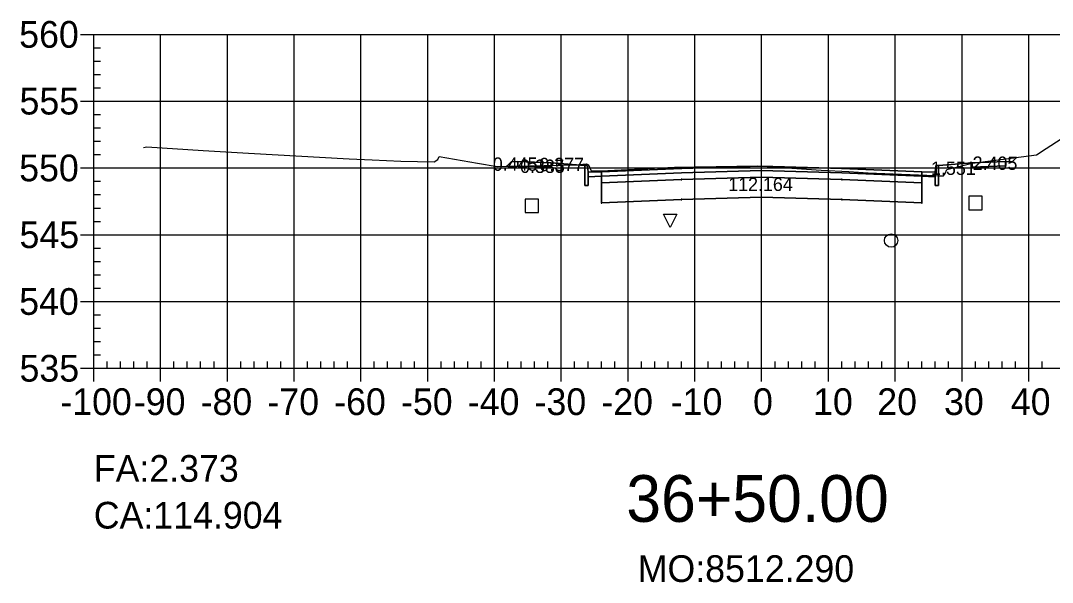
# Model space of a CAD drawing. Extents: x 704834 to 709892, y 372981 to 377533.
# Drawn here: x 707125.9 to 707280.4, y 373920.8 to 374004.9 of the extents above; entities that cross this region are included whole.
import ezdxf

# ---------------------------------------------------------------- set-up
doc = ezdxf.new("R2010")
doc.units = 0
for name, color, linetype in [('1', 7, 'Continuous'), ('10', 7, 'Continuous'), ('13', 7, 'Continuous'), ('14', 7, 'Continuous'), ('4', 7, 'Continuous'), ('57', 7, 'Continuous'), ('59', 7, 'Continuous'), ('Default_Xsect', 7, 'Continuous'), ('Existing', 7, 'Continuous')]:
    doc.layers.add(name, color=color, linetype=linetype)

msp = doc.modelspace()

# ---------------------------------------------------------------- linework, layer by layer
for points in [[(707199.37, 373983.74), (707198.7, 373983.07)], [(707200.37, 373983.78), (707199.37, 373983.74)], [(707210.37, 373983.18), (707205.37, 373983.58)], [(707263.37, 373983.18), (707268.37, 373983.58)], [(707273.37, 373983.78), (707274.37, 373983.74)], [(707274.37, 373983.74), (707275.04, 373984.4)]]:
    msp.add_lwpolyline(points)
for points in [[(707205.37, 373983.58), (707200.37, 373983.78), (707200.37, 373983.11), (707205.37, 373982.91)], [(707210.87, 373982.18), (707210.79, 373983.18), (707210.37, 373983.18), (707210.37, 373980.18), (707210.87, 373980.18)], [(707236.87, 373982.43), (707248.87, 373982.07), (707260.87, 373981.59), (707260.87, 373982.26), (707248.87, 373982.74), (707236.87, 373983.1), (707224.87, 373982.74), (707212.87, 373982.26), (707212.87, 373981.59), (707224.87, 373982.07)], [(707262.87, 373980.18), (707263.37, 373980.18), (707263.37, 373983.18), (707262.96, 373983.18), (707262.87, 373982.18)], [(707268.37, 373982.91), (707273.37, 373983.11), (707273.37, 373983.78), (707268.37, 373983.58)], [(707212.87, 373982.26), (707210.87, 373982.18), (707210.87, 373981.51), (707212.87, 373981.59)], [(707236.87, 373981.43), (707248.87, 373981.07), (707260.87, 373980.59), (707260.87, 373981.59), (707248.87, 373982.07), (707236.87, 373982.43), (707224.87, 373982.07), (707212.87, 373981.59), (707212.87, 373980.59), (707224.87, 373981.07)], [(707236.87, 373978.43), (707248.87, 373978.07), (707260.87, 373977.59), (707260.87, 373980.59), (707248.87, 373981.07), (707236.87, 373981.43), (707224.87, 373981.07), (707212.87, 373980.59), (707212.87, 373977.59), (707224.87, 373978.07)], [(707236.82, 373982.38), (707236.92, 373982.38), (707236.92, 373982.48), (707236.82, 373982.48)], [(707236.82, 373981.38), (707236.92, 373981.38), (707236.92, 373981.48), (707236.82, 373981.48)], [(707260.87, 373981.59), (707262.87, 373981.51), (707262.87, 373982.18), (707260.87, 373982.26)], [(707212.82, 373980.54), (707212.92, 373980.54), (707212.92, 373980.64), (707212.82, 373980.64)], [(707224.82, 373981.02), (707224.92, 373981.02), (707224.92, 373981.12), (707224.82, 373981.12)], [(707248.82, 373981.02), (707248.92, 373981.02), (707248.92, 373981.12), (707248.82, 373981.12)], [(707260.82, 373980.54), (707260.92, 373980.54), (707260.92, 373980.64), (707260.82, 373980.64)], [(707236.82, 373978.38), (707236.92, 373978.38), (707236.92, 373978.48), (707236.82, 373978.48)], [(707212.82, 373977.54), (707212.92, 373977.54), (707212.92, 373977.64), (707212.82, 373977.64)], [(707224.82, 373978.02), (707224.92, 373978.02), (707224.92, 373978.12), (707224.82, 373978.12)], [(707248.82, 373978.02), (707248.92, 373978.02), (707248.92, 373978.12), (707248.82, 373978.12)], [(707260.82, 373977.54), (707260.92, 373977.54), (707260.92, 373977.64), (707260.82, 373977.64)]]:
    msp.add_lwpolyline(points, close=True)
at = {"layer": '1'}
for points in [[(707198.7, 373983.07), (707200.59, 373983.1), (707200.37, 373983.11), (707200.37, 373983.78), (707199.37, 373983.74)], [(707200.59, 373983.1), (707205.37, 373983.19), (707205.37, 373982.91)], [(707205.37, 373983.19), (707208.93, 373983.26), (707209.14, 373983.28), (707205.37, 373983.58)], [(707209.14, 373983.28), (707210.62, 373983.41), (707210.89, 373983.35), (707210.92, 373983.28), (707211.34, 373982.38), (707212.82, 373982.41), (707223.83, 373982.95), (707233.14, 373983.07), (707236.27, 373983.12), (707245.8, 373982.5), (707249.91, 373982.27), (707252.83, 373982.09), (707263.37, 373981.65), (707263.37, 373980.18), (707262.87, 373980.18), (707262.87, 373981.51), (707260.87, 373981.59), (707260.87, 373980.59), (707260.87, 373977.59), (707248.87, 373978.07), (707236.87, 373978.43), (707224.87, 373978.07), (707212.87, 373977.59), (707212.87, 373980.59), (707212.87, 373981.59), (707210.87, 373981.51), (707210.87, 373980.18), (707210.37, 373980.18), (707210.37, 373983.18)], [(707263.37, 373981.65), (707264.12, 373981.62), (707264.35, 373982.01), (707264.62, 373982.6), (707267.97, 373983.44), (707268.37, 373983.5), (707268.37, 373983.58), (707263.37, 373983.18)], [(707268.37, 373983.5), (707268.44, 373983.51), (707275.04, 373984.4), (707274.37, 373983.74), (707273.37, 373983.78), (707273.37, 373983.11), (707268.37, 373982.91)], [(707223.16, 373973.92), (707222.16, 373975.92), (707224.16, 373975.92)]]:
    msp.add_lwpolyline(points, close=True, dxfattribs=at)
at = {"layer": '10'}
msp.add_lwpolyline([(707201.46, 373976.14), (707203.46, 373976.14), (707203.46, 373978.14), (707201.46, 373978.14)], close=True, dxfattribs=at)
at = {"layer": '13'}
msp.add_circle((707256.26, 373971.95), 1, dxfattribs=at)
at = {"layer": '14'}
for points in [[(707198.7, 373983.07), (707198.7, 373983.12), (707198.7, 373983.07), (707198.65, 373983.07), (707198.7, 373983.07), (707198.7, 373983.02), (707198.7, 373983.07), (707198.75, 373983.07)], [(707236.87, 373983.1), (707236.87, 373983.15), (707236.87, 373983.1), (707236.82, 373983.1), (707236.87, 373983.1), (707236.87, 373983.05), (707236.87, 373983.1), (707236.92, 373983.1)], [(707275.04, 373984.4), (707275.04, 373984.45), (707275.04, 373984.4), (707274.99, 373984.4), (707275.04, 373984.4), (707275.04, 373984.35), (707275.04, 373984.4), (707275.09, 373984.4)], [(707212.87, 373982.26), (707212.87, 373982.31), (707212.87, 373982.26), (707212.82, 373982.26), (707212.87, 373982.26), (707212.87, 373982.21), (707212.87, 373982.26), (707212.92, 373982.26)], [(707224.87, 373982.74), (707224.87, 373982.79), (707224.87, 373982.74), (707224.82, 373982.74), (707224.87, 373982.74), (707224.87, 373982.69), (707224.87, 373982.74), (707224.92, 373982.74)], [(707248.87, 373982.74), (707248.87, 373982.79), (707248.87, 373982.74), (707248.82, 373982.74), (707248.87, 373982.74), (707248.87, 373982.69), (707248.87, 373982.74), (707248.92, 373982.74)], [(707260.87, 373982.26), (707260.87, 373982.31), (707260.87, 373982.26), (707260.82, 373982.26), (707260.87, 373982.26), (707260.87, 373982.21), (707260.87, 373982.26), (707260.92, 373982.26)]]:
    msp.add_lwpolyline(points, dxfattribs=at)
at = {"layer": '4'}
msp.add_lwpolyline([(707267.91, 373976.57), (707269.91, 373976.57), (707269.91, 373978.57), (707267.91, 373978.57)], close=True, dxfattribs=at)
at = {"layer": '57'}
for p, q in [((707134.87, 374002.82), (707136.87, 374002.82)), ((707136.87, 374002.82), (707336.87, 374002.82)), ((707136.87, 373952.82), (707136.87, 374002.82)), ((707136.87, 373952.82), (707136.87, 374002.82)), ((707146.87, 373952.82), (707146.87, 374002.82)), ((707156.87, 373952.82), (707156.87, 374002.82)), ((707166.87, 373952.82), (707166.87, 374002.82)), ((707176.87, 373952.82), (707176.87, 374002.82)), ((707186.87, 373952.82), (707186.87, 374002.82)), ((707196.87, 373952.82), (707196.87, 374002.82)), ((707206.87, 373952.82), (707206.87, 374002.82)), ((707216.87, 373952.82), (707216.87, 374002.82)), ((707226.87, 373952.82), (707226.87, 374002.82)), ((707236.87, 373952.82), (707236.87, 374002.82)), ((707246.87, 373952.82), (707246.87, 374002.82)), ((707256.87, 373952.82), (707256.87, 374002.82)), ((707266.87, 373952.82), (707266.87, 374002.82)), ((707276.87, 373952.82), (707276.87, 374002.82)), ((707136.87, 374000.82), (707137.87, 374000.82)), ((707136.87, 373998.82), (707137.87, 373998.82)), ((707136.87, 373996.82), (707137.87, 373996.82)), ((707136.87, 373994.82), (707137.87, 373994.82)), ((707134.87, 373992.82), (707136.87, 373992.82)), ((707136.87, 373992.82), (707336.87, 373992.82)), ((707136.87, 373990.82), (707137.87, 373990.82)), ((707136.87, 373988.82), (707137.87, 373988.82)), ((707136.87, 373986.82), (707137.87, 373986.82)), ((707136.87, 373984.82), (707137.87, 373984.82)), ((707134.87, 373982.82), (707136.87, 373982.82)), ((707136.87, 373982.82), (707336.87, 373982.82)), ((707136.87, 373980.82), (707137.87, 373980.82)), ((707136.87, 373978.82), (707137.87, 373978.82)), ((707136.87, 373976.82), (707137.87, 373976.82)), ((707136.87, 373974.82), (707137.87, 373974.82)), ((707134.87, 373972.82), (707136.87, 373972.82)), ((707136.87, 373972.82), (707336.87, 373972.82)), ((707136.87, 373970.82), (707137.87, 373970.82)), ((707136.87, 373968.82), (707137.87, 373968.82)), ((707136.87, 373966.82), (707137.87, 373966.82)), ((707136.87, 373964.82), (707137.87, 373964.82)), ((707134.87, 373962.82), (707136.87, 373962.82)), ((707136.87, 373962.82), (707336.87, 373962.82)), ((707136.87, 373960.82), (707137.87, 373960.82)), ((707136.87, 373958.82), (707137.87, 373958.82)), ((707136.87, 373956.82), (707137.87, 373956.82)), ((707136.87, 373954.82), (707137.87, 373954.82)), ((707138.87, 373952.82), (707138.87, 373953.82)), ((707140.87, 373952.82), (707140.87, 373953.82)), ((707142.87, 373952.82), (707142.87, 373953.82)), ((707144.87, 373952.82), (707144.87, 373953.82)), ((707148.87, 373952.82), (707148.87, 373953.82)), ((707150.87, 373952.82), (707150.87, 373953.82)), ((707152.87, 373952.82), (707152.87, 373953.82)), ((707154.87, 373952.82), (707154.87, 373953.82)), ((707158.87, 373952.82), (707158.87, 373953.82)), ((707160.87, 373952.82), (707160.87, 373953.82)), ((707162.87, 373952.82), (707162.87, 373953.82)), ((707164.87, 373952.82), (707164.87, 373953.82)), ((707168.87, 373952.82), (707168.87, 373953.82)), ((707170.87, 373952.82), (707170.87, 373953.82)), ((707172.87, 373952.82), (707172.87, 373953.82)), ((707174.87, 373952.82), (707174.87, 373953.82)), ((707178.87, 373952.82), (707178.87, 373953.82)), ((707180.87, 373952.82), (707180.87, 373953.82)), ((707182.87, 373952.82), (707182.87, 373953.82)), ((707184.87, 373952.82), (707184.87, 373953.82)), ((707188.87, 373952.82), (707188.87, 373953.82)), ((707190.87, 373952.82), (707190.87, 373953.82)), ((707192.87, 373952.82), (707192.87, 373953.82)), ((707194.87, 373952.82), (707194.87, 373953.82)), ((707198.87, 373952.82), (707198.87, 373953.82)), ((707200.87, 373952.82), (707200.87, 373953.82)), ((707202.87, 373952.82), (707202.87, 373953.82)), ((707204.87, 373952.82), (707204.87, 373953.82)), ((707208.87, 373952.82), (707208.87, 373953.82)), ((707210.87, 373952.82), (707210.87, 373953.82)), ((707212.87, 373952.82), (707212.87, 373953.82)), ((707214.87, 373952.82), (707214.87, 373953.82)), ((707218.87, 373952.82), (707218.87, 373953.82)), ((707220.87, 373952.82), (707220.87, 373953.82)), ((707222.87, 373952.82), (707222.87, 373953.82)), ((707224.87, 373952.82), (707224.87, 373953.82)), ((707228.87, 373952.82), (707228.87, 373953.82)), ((707230.87, 373952.82), (707230.87, 373953.82)), ((707232.87, 373952.82), (707232.87, 373953.82)), ((707234.87, 373952.82), (707234.87, 373953.82)), ((707238.87, 373952.82), (707238.87, 373953.82)), ((707240.87, 373952.82), (707240.87, 373953.82)), ((707242.87, 373952.82), (707242.87, 373953.82)), ((707244.87, 373952.82), (707244.87, 373953.82)), ((707248.87, 373952.82), (707248.87, 373953.82)), ((707250.87, 373952.82), (707250.87, 373953.82)), ((707252.87, 373952.82), (707252.87, 373953.82)), ((707254.87, 373952.82), (707254.87, 373953.82)), ((707258.87, 373952.82), (707258.87, 373953.82)), ((707260.87, 373952.82), (707260.87, 373953.82)), ((707262.87, 373952.82), (707262.87, 373953.82)), ((707264.87, 373952.82), (707264.87, 373953.82)), ((707268.87, 373952.82), (707268.87, 373953.82)), ((707270.87, 373952.82), (707270.87, 373953.82)), ((707272.87, 373952.82), (707272.87, 373953.82)), ((707274.87, 373952.82), (707274.87, 373953.82)), ((707278.87, 373952.82), (707278.87, 373953.82)), ((707134.87, 373952.82), (707136.87, 373952.82)), ((707136.87, 373952.82), (707336.87, 373952.82)), ((707136.87, 373952.82), (707336.87, 373952.82)), ((707136.87, 373950.82), (707136.87, 373952.82)), ((707146.87, 373950.82), (707146.87, 373952.82)), ((707156.87, 373950.82), (707156.87, 373952.82)), ((707166.87, 373950.82), (707166.87, 373952.82)), ((707176.87, 373950.82), (707176.87, 373952.82)), ((707186.87, 373950.82), (707186.87, 373952.82)), ((707196.87, 373950.82), (707196.87, 373952.82)), ((707206.87, 373950.82), (707206.87, 373952.82)), ((707216.87, 373950.82), (707216.87, 373952.82)), ((707226.87, 373950.82), (707226.87, 373952.82)), ((707236.87, 373950.82), (707236.87, 373952.82)), ((707246.87, 373950.82), (707246.87, 373952.82)), ((707256.87, 373950.82), (707256.87, 373952.82)), ((707266.87, 373950.82), (707266.87, 373952.82)), ((707276.87, 373950.82), (707276.87, 373952.82))]:
    msp.add_line(p, q, dxfattribs=at)
at = {"layer": 'Default_Xsect'}
msp.add_lwpolyline([(707198.7, 373983.07), (707199.37, 373983.74), (707200.37, 373983.78), (707205.37, 373983.58), (707210.37, 373983.18), (707210.79, 373983.18), (707210.87, 373982.18), (707212.87, 373982.26), (707224.87, 373982.74), (707236.87, 373983.1), (707248.87, 373982.74), (707260.87, 373982.26), (707262.87, 373982.18), (707262.96, 373983.18), (707263.37, 373983.18), (707268.37, 373983.58), (707273.37, 373983.78), (707274.37, 373983.74), (707275.04, 373984.4)], dxfattribs=at)
at = {"layer": 'Existing'}
msp.add_lwpolyline([(707144.29, 373985.89), (707144.83, 373985.99), (707153.26, 373985.45), (707160.03, 373985.03), (707175.13, 373984.16), (707178.55, 373984.03), (707182.86, 373983.83), (707187.83, 373983.74), (707188.36, 373984.06), (707188.57, 373984.51), (707194.33, 373983.55), (707197.26, 373983.04), (707208.93, 373983.26), (707210.62, 373983.41), (707210.89, 373983.35), (707210.92, 373983.28), (707211.34, 373982.38), (707212.82, 373982.41), (707223.83, 373982.95), (707233.14, 373983.07), (707236.27, 373983.12), (707245.8, 373982.5), (707249.91, 373982.27), (707252.83, 373982.09), (707264.12, 373981.62), (707264.35, 373982.01), (707264.62, 373982.6), (707267.97, 373983.44), (707268.44, 373983.51), (707278, 373984.8), (707279.48, 373985.74), (707281.72, 373987.19)], dxfattribs=at)

# ---------------------------------------------------------------- texts
msp.add_text('CA:114.904', height=4).set_placement((707136.87, 373928.82))
at = {"layer": '1'}
msp.add_text('36+50.00', height=7, dxfattribs=at).set_placement((707216.6, 373929.82))
at = {"layer": '14'}
for p in [(707200.34, 373983.73), (707200.34, 373983.06), (707273.34, 373983.73), (707273.34, 373983.06), (707205.34, 373982.86), (707268.34, 373982.86)]:
    msp.add_text('+', height=0.1, dxfattribs=at).set_placement(p)
at = {"layer": '57'}
for s, p in [('560', (707125.7, 374000.82)), ('555', (707125.75, 373990.82)), ('550', (707125.7, 373980.82)), ('545', (707125.75, 373970.82)), ('540', (707125.7, 373960.82)), ('535', (707125.75, 373950.82)), ('-100', (707131.86, 373945.82)), ('-90', (707142.87, 373945.82)), ('-80', (707152.87, 373945.82)), ('-70', (707162.87, 373945.82)), ('-60', (707172.87, 373945.82)), ('-50', (707182.87, 373945.82)), ('-40', (707192.87, 373945.82)), ('-30', (707202.87, 373945.82)), ('-20', (707212.87, 373945.82)), ('-10', (707223.26, 373945.82)), ('0', (707235.58, 373945.82)), ('10', (707244.57, 373945.82)), ('20', (707254.18, 373945.82)), ('30', (707264.18, 373945.82)), ('40', (707274.18, 373945.82))]:
    msp.add_text(s, height=4, dxfattribs=at).set_placement(p)
at = {"layer": '59'}
for s, height, p in [('2.405', 2, (707268.46, 373982.53)), ('0.445', 2, (707196.62, 373982.39)), ('0.335', 2, (707200.7, 373982.07)), ('0.377', 2, (707203.58, 373982.34)), ('1.551', 2, (707262.23, 373981.78)), ('112.164', 2, (707231.86, 373979.37)), ('FA:2.373', 4, (707136.87, 373935.82)), ('MO:8512.290', 4, (707218.31, 373920.82))]:
    msp.add_text(s, height=height, dxfattribs=at).set_placement(p)

doc.saveas('drawing.dxf')
